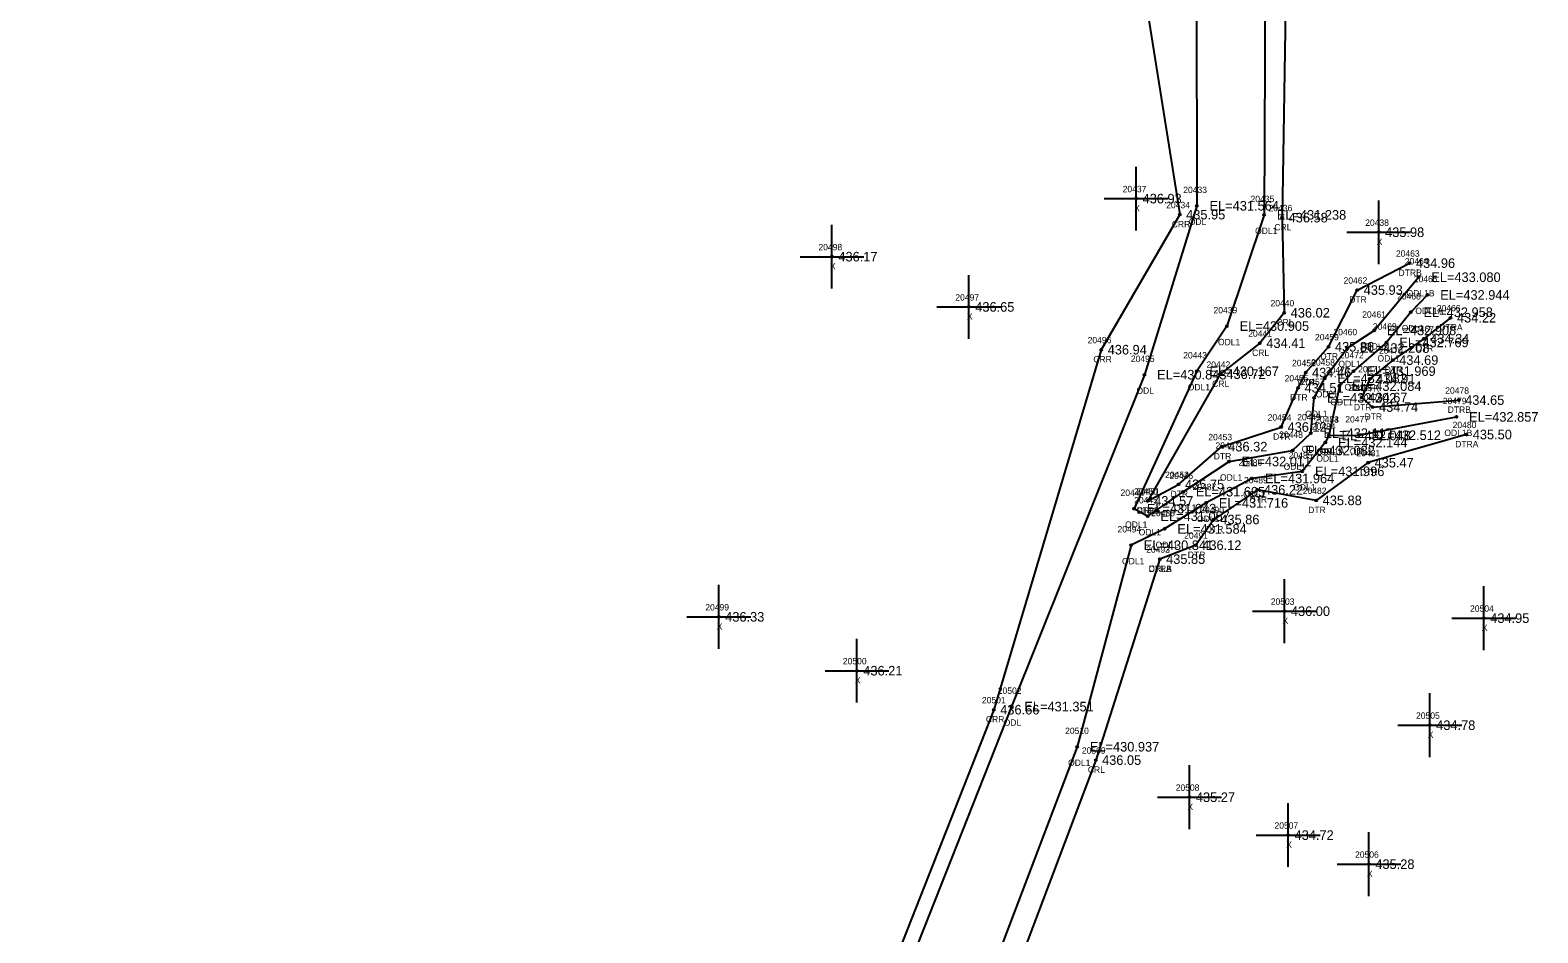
# Model space of a CAD drawing. Extents: x 1613836 to 1615109, y 777151 to 778248.
# Drawn here: x 1614435.8 to 1614672.1, y 777942.5 to 778084 of the extents above; entities that cross this region are included whole.
import ezdxf

# ---------------------------------------------------------------- set-up
doc = ezdxf.new("R2010")
doc.units = 0
for name, color, linetype in [('RD_EX_H2O', 7, 'Continuous'), ('RD_EX_H2O_txCode', 7, 'Continuous'), ('RD_EX_Misc', 7, 'Continuous'), ('RD_EX_Misc_txCode', 7, 'Continuous'), ('RD_EX_TX_H2O_ELEV', 7, 'Continuous'), ('RD_EX_TX_Misc_ELEV', 7, 'Continuous'), ('RD_SMD_Locator', 7, 'Continuous')]:
    doc.layers.add(name, color=color, linetype=linetype)

msp = doc.modelspace()

# ---------------------------------------------------------------- linework, layer by layer
at = {"layer": 'RD_EX_H2O'}
for points in [[(1614634.13, 778230.42), (1614629.46, 778175.6), (1614612.2, 778126.55), (1614606.67, 778108.17), (1614610.57, 778089.24), (1614615.98, 778055.09), (1614603.68, 778033.92), (1614586.84, 777977.49), (1614567.11, 777927.46), (1614559.23, 777908.74), (1614527.56, 777868.79), (1614521.38, 777849.92), (1614508, 777820.03), (1614493.75, 777779.64), (1614479.27, 777749.87), (1614469.02, 777727.63), (1614464.37, 777721.67), (1614444.52, 777689.77), (1614435.76, 777671.49)], [(1614639.54, 778230.63), (1614634.52, 778174.88), (1614617.02, 778127.08), (1614609.96, 778108.29), (1614618.6, 778090.08), (1614618.65, 778056.48), (1614610.43, 778030), (1614589.62, 777977.97), (1614569.81, 777927.89), (1614565.63, 777909.32), (1614534.03, 777865.55), (1614528.13, 777847.05), (1614516.47, 777815.91), (1614496.55, 777778.36), (1614481.67, 777748.03), (1614471.7, 777724.98), (1614468.53, 777719.48), (1614464.55, 777708.61), (1614459.06, 777697.65), (1614451.34, 777685.51), (1614441.64, 777670.36)], [(1614647.5, 778227.95), (1614643.37, 778173.13), (1614623.82, 778123.38), (1614615.86, 778110.4), (1614618.74, 778101.49), (1614629.36, 778091.54), (1614629.2, 778055.05), (1614623.38, 778037.62), (1614618.64, 778030.54), (1614608.82, 778009), (1614610.95, 778007.82), (1614616.5, 778011.66), (1614623.7, 778016.39), (1614633.68, 778018.1), (1614636.51, 778020.84), (1614637.06, 778026.36), (1614638.7, 778029.43), (1614642.25, 778034.18), (1614646.44, 778036.94), (1614653.41, 778045.28)], [(1614652.57, 778227.35), (1614649.11, 778172.15), (1614632.08, 778118.24), (1614628.2, 778108.38), (1614631.09, 778101.39), (1614632.62, 778090.53), (1614632.04, 778054.62), (1614632.37, 778039.71), (1614628.55, 778034.94), (1614622.29, 778030.08), (1614610.97, 778010.21)], [(1614610.97, 778010.21), (1614615.8, 778012.81), (1614622.58, 778018.72), (1614631.88, 778021.8), (1614634.54, 778027.94), (1614635.72, 778030.33), (1614639.31, 778034.38), (1614643.81, 778043.27), (1614652.01, 778047.49)], [(1614654.81, 778042.5), (1614652.19, 778039.79), (1614648.39, 778035.06), (1614643.22, 778030.56), (1614641, 778028.21), (1614639.33, 778020.47), (1614644.05, 778020.51), (1614659.34, 778023.38)], [(1614658.44, 778038.93), (1614654.25, 778035.64), (1614649.38, 778032.29), (1614645.79, 778029.35), (1614644.54, 778026.43), (1614646.22, 778024.93), (1614659.72, 778026.02)], [(1614639.33, 778020.47), (1614638.8, 778019.37), (1614635.18, 778014.85), (1614627.32, 778013.74), (1614620.1, 778009.9), (1614613.61, 778005.82), (1614608.34, 778003.27), (1614599.89, 777971.68), (1614580.65, 777921.1), (1614573.17, 777903.34), (1614544.02, 777862.61), (1614536.62, 777846.2), (1614525.93, 777814.9), (1614525.36, 777805.04), (1614514.83, 777790.8), (1614507.45, 777775.73), (1614494.22, 777745.87), (1614477.07, 777716.66), (1614470.86, 777703.72), (1614467.03, 777692.39), (1614458.98, 777681.06), (1614454.05, 777670.72)], [(1614660.91, 778020.62), (1614645.52, 778016.21), (1614637.38, 778010.3), (1614628.18, 778011.96), (1614621.34, 778007.3), (1614618.51, 778003.28), (1614612.84, 778001.09)], [(1614612.84, 778001.09), (1614602.8, 777969.59), (1614583.96, 777919.69), (1614574.96, 777902.32), (1614550.82, 777861.38), (1614543.23, 777842.17), (1614528.68, 777813.75), (1614526.1, 777801.65), (1614517.13, 777789.52), (1614510.38, 777774.58), (1614495.52, 777745.97), (1614480.57, 777714.78), (1614474.46, 777705.96), (1614477.93, 777705.13), (1614481.15, 777703.4), (1614481.27, 777700.99), (1614480.97, 777699.74), (1614478.44, 777696.16), (1614475.82, 777697.62), (1614468.32, 777689.25), (1614463.06, 777676.24), (1614459.87, 777668.19)]]:
    msp.add_lwpolyline(points, dxfattribs=at)
at = {"layer": 'RD_EX_Misc'}
for p, q in [((1614609.15, 778052.6), (1614609.15, 778062.6)), ((1614604.15, 778057.6), (1614614.15, 778057.6)), ((1614647.17, 778047.33), (1614647.17, 778057.33)), ((1614561.46, 778043.5), (1614561.46, 778053.5)), ((1614642.17, 778052.33), (1614652.17, 778052.33)), ((1614556.46, 778048.5), (1614566.46, 778048.5)), ((1614582.92, 778035.62), (1614582.92, 778045.62)), ((1614577.92, 778040.62), (1614587.92, 778040.62)), ((1614543.72, 777987.04), (1614543.72, 777997.04)), ((1614632.4, 777987.93), (1614632.4, 777997.93)), ((1614663.65, 777986.84), (1614663.65, 777996.84)), ((1614627.4, 777992.93), (1614637.4, 777992.93)), ((1614538.72, 777992.04), (1614548.72, 777992.04)), ((1614658.65, 777991.84), (1614668.65, 777991.84)), ((1614565.37, 777978.6), (1614565.37, 777988.6)), ((1614560.37, 777983.6), (1614570.37, 777983.6)), ((1614655.18, 777970.06), (1614655.18, 777980.06)), ((1614650.18, 777975.06), (1614660.18, 777975.06)), ((1614617.51, 777958.77), (1614617.51, 777968.77)), ((1614612.51, 777963.77), (1614622.51, 777963.77)), ((1614632.98, 777952.83), (1614632.98, 777962.83)), ((1614627.98, 777957.83), (1614637.98, 777957.83)), ((1614645.64, 777948.27), (1614645.64, 777958.27)), ((1614640.64, 777953.27), (1614650.64, 777953.27))]:
    msp.add_line(p, q, dxfattribs=at)
at = {"layer": 'RD_SMD_Locator'}
for centre in [(1614609.15, 778057.6), (1614618.65, 778056.48), (1614615.98, 778055.09), (1614629.2, 778055.05), (1614632.04, 778054.62), (1614647.17, 778052.33), (1614561.46, 778048.5), (1614652.01, 778047.49), (1614653.41, 778045.28), (1614643.81, 778043.27), (1614654.81, 778042.5), (1614582.92, 778040.62), (1614632.37, 778039.71), (1614652.19, 778039.79), (1614623.38, 778037.62), (1614658.44, 778038.93), (1614628.55, 778034.94), (1614646.44, 778036.94), (1614648.39, 778035.06), (1614654.25, 778035.64), (1614603.68, 778033.92), (1614639.31, 778034.38), (1614642.25, 778034.18), (1614610.43, 778030), (1614618.64, 778030.54), (1614622.29, 778030.08), (1614635.72, 778030.33), (1614643.22, 778030.56), (1614649.38, 778032.29), (1614634.54, 778027.94), (1614638.7, 778029.43), (1614641, 778028.21), (1614645.79, 778029.35), (1614637.06, 778026.36), (1614644.54, 778026.43), (1614659.72, 778026.02), (1614646.22, 778024.93), (1614659.34, 778023.38), (1614631.88, 778021.8), (1614636.51, 778020.84), (1614644.05, 778020.51), (1614660.91, 778020.62), (1614622.58, 778018.72), (1614638.8, 778019.37), (1614639.33, 778020.47), (1614639.33, 778020.47), (1614623.7, 778016.39), (1614633.68, 778018.1), (1614645.52, 778016.21), (1614627.32, 778013.74), (1614635.18, 778014.85), (1614615.8, 778012.81), (1614616.5, 778011.66), (1614628.18, 778011.96), (1614608.82, 778009), (1614610.97, 778010.21), (1614610.97, 778010.21), (1614620.1, 778009.9), (1614637.38, 778010.3), (1614610.95, 778007.82), (1614621.34, 778007.3), (1614613.61, 778005.82), (1614608.34, 778003.27), (1614618.51, 778003.28), (1614612.84, 778001.09), (1614612.84, 778001.09), (1614632.4, 777992.93), (1614543.72, 777992.04), (1614663.65, 777991.84), (1614565.37, 777983.6), (1614589.62, 777977.97), (1614586.84, 777977.49), (1614655.18, 777975.06), (1614599.89, 777971.68), (1614602.8, 777969.59), (1614617.51, 777963.77), (1614632.98, 777957.83), (1614645.64, 777953.27)]:
    msp.add_circle(centre, 0.15, dxfattribs=at)

# ---------------------------------------------------------------- texts
at = {"layer": 'RD_EX_H2O_txCode'}
for s, p in [('20433', (1614616.53, 778058.48)), ('20434', (1614613.86, 778056.09)), ('20435', (1614627.08, 778057.05)), ('20436', (1614629.9, 778055.62)), ('CRR', (1614614.73, 778053.09)), ('ODL', (1614617.4, 778053.48)), ('ODL1', (1614627.79, 778052.05)), ('CRL', (1614630.81, 778052.62)), ('20463', (1614649.87, 778048.49)), ('20464', (1614651.27, 778047.28)), ('20462', (1614641.66, 778044.27)), ('DTRB', (1614650.27, 778045.49)), ('20465', (1614652.67, 778044.5)), ('DTR', (1614642.54, 778041.27)), ('20468', (1614650.05, 778041.79)), ('ODL1B', (1614651.53, 778042.28)), ('20439', (1614621.27, 778039.62)), ('20440', (1614630.21, 778040.71)), ('20461', (1614644.58, 778038.94)), ('ODL1A', (1614652.91, 778039.5)), ('20466', (1614656.27, 778039.93)), ('CRL', (1614631.14, 778037.71)), ('20460', (1614640.07, 778036.18)), ('20469', (1614646.25, 778037.06)), ('ODL1', (1614650.78, 778036.79)), ('20467', (1614652.11, 778036.64)), ('DTRA', (1614656.68, 778036.93)), ('20496', (1614601.54, 778034.92)), ('ODL1', (1614621.97, 778034.62)), ('20441', (1614626.71, 778035.94)), ('20459', (1614637.19, 778035.38)), ('ODL1', (1614645.03, 778033.94)), ('CRR', (1614602.43, 778031.92)), ('20495', (1614608.32, 778032)), ('20443', (1614616.52, 778032.54)), ('CRL', (1614627.32, 778032.94)), ('DTR', (1614638.04, 778032.38)), ('20472', (1614641.1, 778032.56)), ('ODL1', (1614646.98, 778032.06)), ('20470', (1614647.22, 778033.29)), ('DTR', (1614652.98, 778033.64)), ('20442', (1614620.17, 778031.08)), ('20456', (1614633.58, 778031.33)), ('20458', (1614636.58, 778031.43)), ('20473', (1614638.88, 778030.21)), ('ODL1', (1614640.84, 778031.18)), ('20471', (1614643.95, 778030.35)), ('DTR', (1614648.11, 778030.29)), ('ODL', (1614609.19, 778027)), ('ODL1', (1614617.23, 778027.54)), ('CRL', (1614621.06, 778028.08)), ('20455', (1614632.42, 778028.94)), ('DTR', (1614634.46, 778028.33)), ('20457', (1614634.94, 778028.36)), ('ODL1', (1614641.81, 778027.56)), ('20475', (1614642.43, 778027.43)), ('DTR', (1614644.52, 778027.35)), ('20478', (1614657.6, 778027.02)), ('DTR', (1614633.27, 778025.94)), ('ODL1', (1614637.29, 778026.43)), ('ODL1', (1614639.59, 778025.21)), ('DTR', (1614643.28, 778024.43)), ('20476', (1614644.07, 778025.93)), ('20479', (1614657.22, 778025.38)), ('20454', (1614629.76, 778022.8)), ('20449', (1614634.39, 778022.84)), ('ODL1', (1614635.65, 778023.36)), ('20474', (1614637.21, 778022.47)), ('20483', (1614637.21, 778022.47)), ('20477', (1614641.93, 778022.51)), ('DTR', (1614644.95, 778022.93)), ('DTRB', (1614657.98, 778024.02)), ('20453', (1614620.46, 778019.72)), ('DTR', (1614630.61, 778019.8)), ('20448', (1614631.57, 778020.1)), ('20484', (1614636.68, 778021.37)), ('ODL1B', (1614657.46, 778020.38)), ('20480', (1614658.76, 778021.62)), ('20447', (1614621.58, 778018.39)), ('ODL1', (1614635.1, 778017.84)), ('ODL1A', (1614637.43, 778017.47)), ('ODL1', (1614637.92, 778017.47)), ('ODL1', (1614642.64, 778017.51)), ('DTRA', (1614659.16, 778018.62)), ('DTR', (1614621.31, 778016.72)), ('20486', (1614625.18, 778015.74)), ('ODL1', (1614632.27, 778015.1)), ('20485', (1614633.06, 778016.85)), ('ODL1', (1614637.39, 778016.37)), ('20481', (1614643.68, 778017.21)), ('20452', (1614613.68, 778013.81)), ('20446', (1614614.36, 778013.66)), ('ODL1', (1614622.29, 778013.39)), ('20489', (1614626.06, 778012.96)), ('DTR', (1614644.25, 778014.21)), ('20444', (1614606.7, 778011)), ('20450', (1614608.81, 778011.21)), ('20451', (1614609.13, 778011.21)), ('DTR', (1614614.53, 778010.81)), ('20487', (1614617.98, 778011.9)), ('ODL1', (1614625.91, 778010.74)), ('ODL1', (1614633.77, 778011.85)), ('20482', (1614635.26, 778011.3)), ('20445', (1614608.83, 778009.82)), ('DTRA', (1614609.21, 778008.21)), ('CRLB', (1614609.27, 778008.21)), ('20488', (1614611.5, 778007.82)), ('ODL1', (1614615.09, 778008.66)), ('20490', (1614619.19, 778008.3)), ('DTR', (1614626.91, 778009.96)), ('DTR', (1614636.11, 778008.3)), ('ODL1', (1614607.41, 778006)), ('ODL1', (1614618.69, 778006.9)), ('20494', (1614606.22, 778005.27)), ('ODL1', (1614609.54, 778004.82)), ('20491', (1614616.67, 778004.28)), ('DTR', (1614620.07, 778005.3)), ('20492', (1614610.72, 778002.09)), ('20493', (1614610.72, 778002.09)), ('ODL1', (1614612.2, 778002.82)), ('DTR', (1614617.24, 778001.28)), ('ODL1', (1614606.93, 778000.27)), ('CRLA', (1614611.12, 777999.09)), ('DTRB', (1614611.1, 777999.09)), ('20502', (1614587.46, 777979.97)), ('20501', (1614584.97, 777978.49)), ('CRR', (1614585.59, 777975.49)), ('ODL', (1614588.38, 777974.97)), ('20510', (1614598.01, 777973.68)), ('20509', (1614600.64, 777970.59)), ('ODL1', (1614598.48, 777968.68)), ('CRL', (1614601.57, 777967.59))]:
    msp.add_text(s, height=1, dxfattribs=at).set_placement(p)
at = {"layer": 'RD_EX_Misc_txCode'}
for s, p in [('20437', (1614607.03, 778058.6)), ('X', (1614608.84, 778055.6)), ('20438', (1614645.05, 778053.33)), ('20498', (1614559.34, 778049.5)), ('X', (1614646.85, 778050.33)), ('X', (1614561.14, 778046.5)), ('20497', (1614580.8, 778041.62)), ('X', (1614582.61, 778038.62)), ('20503', (1614630.25, 777993.93)), ('20499', (1614541.6, 777993.04)), ('20504', (1614661.49, 777992.84)), ('X', (1614543.4, 777990.04)), ('X', (1614632.09, 777990.93)), ('X', (1614663.33, 777989.84)), ('20500', (1614563.17, 777984.6)), ('X', (1614565.05, 777981.6)), ('20505', (1614653.02, 777976.06)), ('X', (1614654.86, 777973.06)), ('20508', (1614615.35, 777964.77)), ('X', (1614617.19, 777961.77)), ('20507', (1614630.83, 777958.83)), ('X', (1614632.67, 777955.83)), ('20506', (1614643.46, 777954.27)), ('X', (1614645.33, 777951.27))]:
    msp.add_text(s, height=1, dxfattribs=at).set_placement(p)
at = {"layer": 'RD_EX_TX_H2O_ELEV'}
for s, p in [('EL=431.564', (1614620.65, 778055.73)), ('435.95', (1614616.98, 778054.34)), ('EL=431.238', (1614631.2, 778054.3)), ('436.58', (1614633.04, 778053.87)), ('434.96', (1614653.01, 778046.74)), ('EL=433.080', (1614655.41, 778044.53)), ('435.93', (1614644.81, 778042.52)), ('EL=432.944', (1614656.81, 778041.75)), ('436.02', (1614633.37, 778038.96)), ('EL=432.958', (1614654.19, 778039.04)), ('434.22', (1614659.44, 778038.18)), ('EL=430.905', (1614625.38, 778036.87)), ('EL=432.908', (1614648.44, 778036.19)), ('434.41', (1614629.55, 778034.19)), ('435.86', (1614640.31, 778033.63)), ('EL=432.208', (1614644.25, 778033.43)), ('EL=432.769', (1614650.39, 778034.31)), ('434.34', (1614655.25, 778034.89)), ('436.94', (1614604.68, 778033.17)), ('434.69', (1614650.38, 778031.54)), ('EL=430.843', (1614612.43, 778029.25)), ('EL=430.167', (1614620.64, 778029.79)), ('436.72', (1614623.29, 778029.33)), ('434.46', (1614636.72, 778029.58)), ('EL=432.082', (1614640.7, 778028.68)), ('EL=431.969', (1614645.22, 778029.81)), ('434.91', (1614646.79, 778028.6)), ('434.51', (1614635.54, 778027.19)), ('EL=432.084', (1614643, 778027.46)), ('EL=432.202', (1614639.06, 778025.61)), ('434.67', (1614645.54, 778025.68)), ('434.74', (1614647.22, 778024.18)), ('434.65', (1614660.72, 778025.27)), ('EL=432.857', (1614661.34, 778022.63)), ('436.12', (1614632.88, 778021.05)), ('EL=432.117', (1614638.51, 778020.09)), ('EL=432.048', (1614641.33, 778019.72)), ('EL=432.048', (1614641.33, 778019.72)), ('EL=432.512', (1614646.05, 778019.76)), ('435.50', (1614661.91, 778019.87)), ('436.32', (1614623.58, 778017.97)), ('EL=432.082', (1614635.68, 778017.35)), ('EL=432.144', (1614640.8, 778018.62)), ('EL=432.011', (1614625.7, 778015.64)), ('435.47', (1614646.52, 778015.46)), ('435.75', (1614616.8, 778012.06)), ('EL=431.964', (1614629.32, 778012.99)), ('EL=431.996', (1614637.18, 778014.1)), ('EL=431.695', (1614618.5, 778010.91)), ('436.22', (1614629.18, 778011.21)), ('EL=431.043', (1614610.82, 778008.25)), ('434.57', (1614611.97, 778009.46)), ('434.57', (1614611.97, 778009.46)), ('EL=431.716', (1614622.1, 778009.15)), ('435.88', (1614638.38, 778009.55)), ('EL=431.057', (1614612.95, 778007.07)), ('EL=431.584', (1614615.61, 778005.07)), ('435.86', (1614622.34, 778006.55)), ('EL=430.841', (1614610.34, 778002.52)), ('435.85', (1614613.84, 778000.34)), ('435.85', (1614613.84, 778000.34)), ('436.12', (1614619.51, 778002.53)), ('436.66', (1614587.84, 777976.74)), ('EL=431.351', (1614591.62, 777977.22)), ('EL=430.937', (1614601.89, 777970.93)), ('436.05', (1614603.8, 777968.84))]:
    msp.add_text(s, height=1.5, dxfattribs=at).set_placement(p)
at = {"layer": 'RD_EX_TX_Misc_ELEV'}
for s, p in [('436.93', (1614610.15, 778056.85)), ('435.98', (1614648.17, 778051.58)), ('436.17', (1614562.46, 778047.75)), ('436.65', (1614583.92, 778039.87)), ('436.33', (1614544.72, 777991.29)), ('436.00', (1614633.4, 777992.18)), ('434.95', (1614664.65, 777991.09)), ('436.21', (1614566.37, 777982.85)), ('434.78', (1614656.18, 777974.31)), ('435.27', (1614618.51, 777963.02)), ('434.72', (1614633.98, 777957.08)), ('435.28', (1614646.64, 777952.52))]:
    msp.add_text(s, height=1.5, dxfattribs=at).set_placement(p)

doc.saveas('drawing.dxf')
